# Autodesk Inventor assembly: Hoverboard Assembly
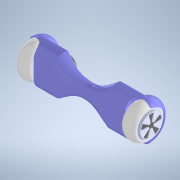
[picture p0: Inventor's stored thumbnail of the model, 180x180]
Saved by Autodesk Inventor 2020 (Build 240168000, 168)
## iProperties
Created: 2020-04
Part Number: Hoverboard Assembly
Document SubType Name: Assembly
Designer: bruno
Author: bruno
Sending System: SolidWorks 2017
Last Author: hpras
Last Saved: 2020-04-24
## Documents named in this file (3)
- C:\Users\bruno\Downloads\hoverboard-18.snapshot.1\Hoverboard Assembly.iam
- C:\Users\bruno\Downloads\hoverboard-18.snapshot.1\Hoverboard.ipt
- C:\Users\bruno\Downloads\hoverboard-18.snapshot.1\Wheel.ipt
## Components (3 placed, 2 different names)
1. Hoverboard:1
2. Wheel:1
3. Wheel:2
